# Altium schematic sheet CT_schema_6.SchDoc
size 367 x 243 mm
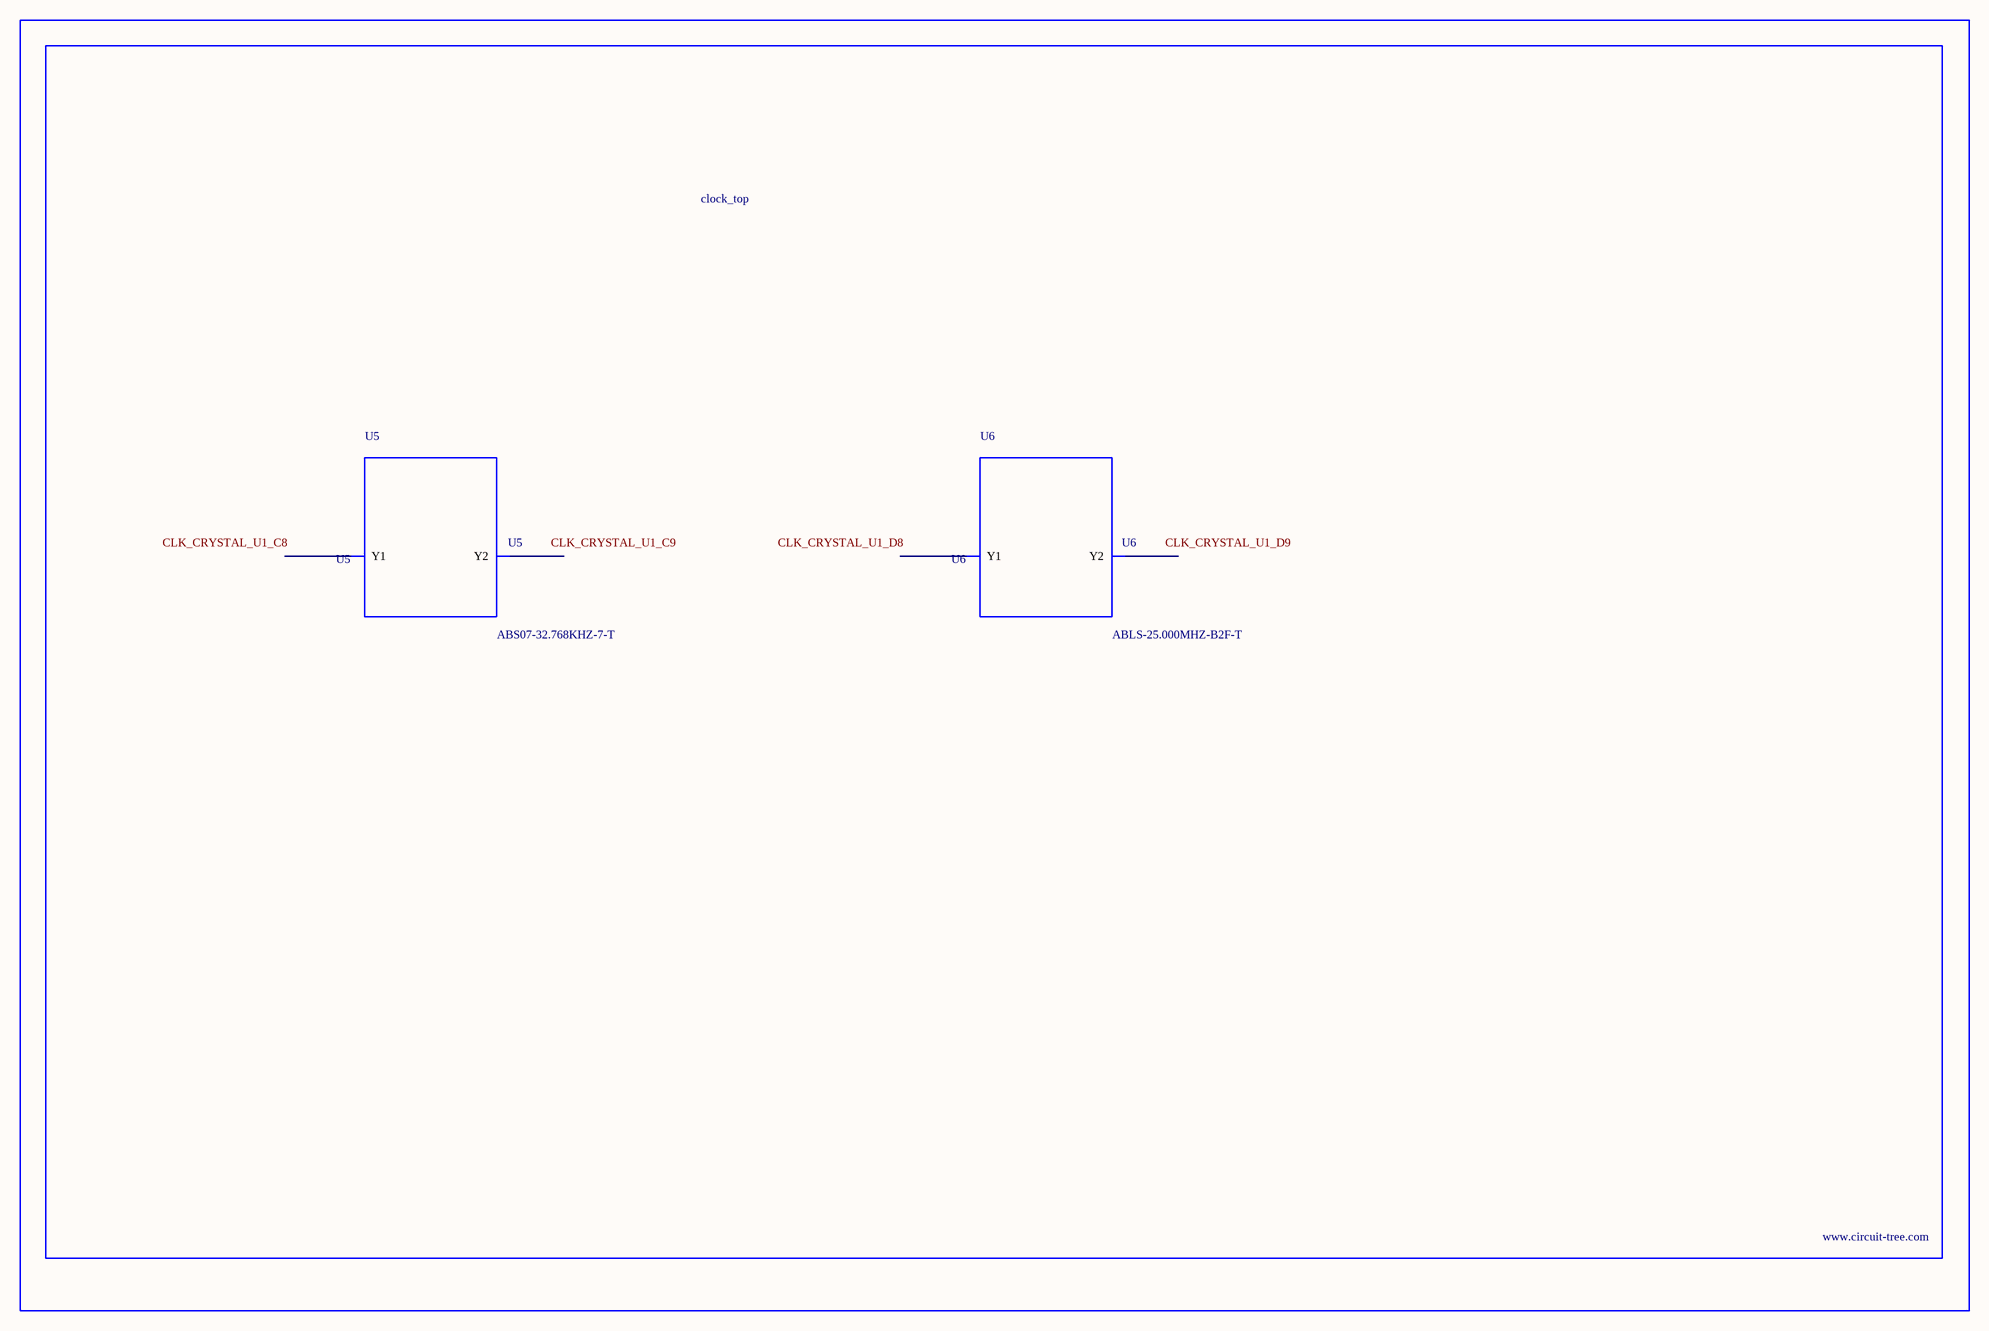
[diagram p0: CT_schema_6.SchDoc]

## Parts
BORDER5  (no value)
U5  ABS07-32.768KHZ-7-T  [ABS07-32.768KHZ-7-T]
U6  ABLS-25.000MHZ-B2F-T  [ABLS-25.000MHZ-B2F-T]

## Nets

Not connected (* = marked no-connect by the designer): U5 1(Y1) 2(Y2); U6 1(Y1) 2(Y2)

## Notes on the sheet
- Labels drawn without touching a wire or pin: CLK_CRYSTAL_U1_C8, CLK_CRYSTAL_U1_C9, CLK_CRYSTAL_U1_D8, CLK_CRYSTAL_U1_D9

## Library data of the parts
BORDER5 = BORDER_PAGE5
